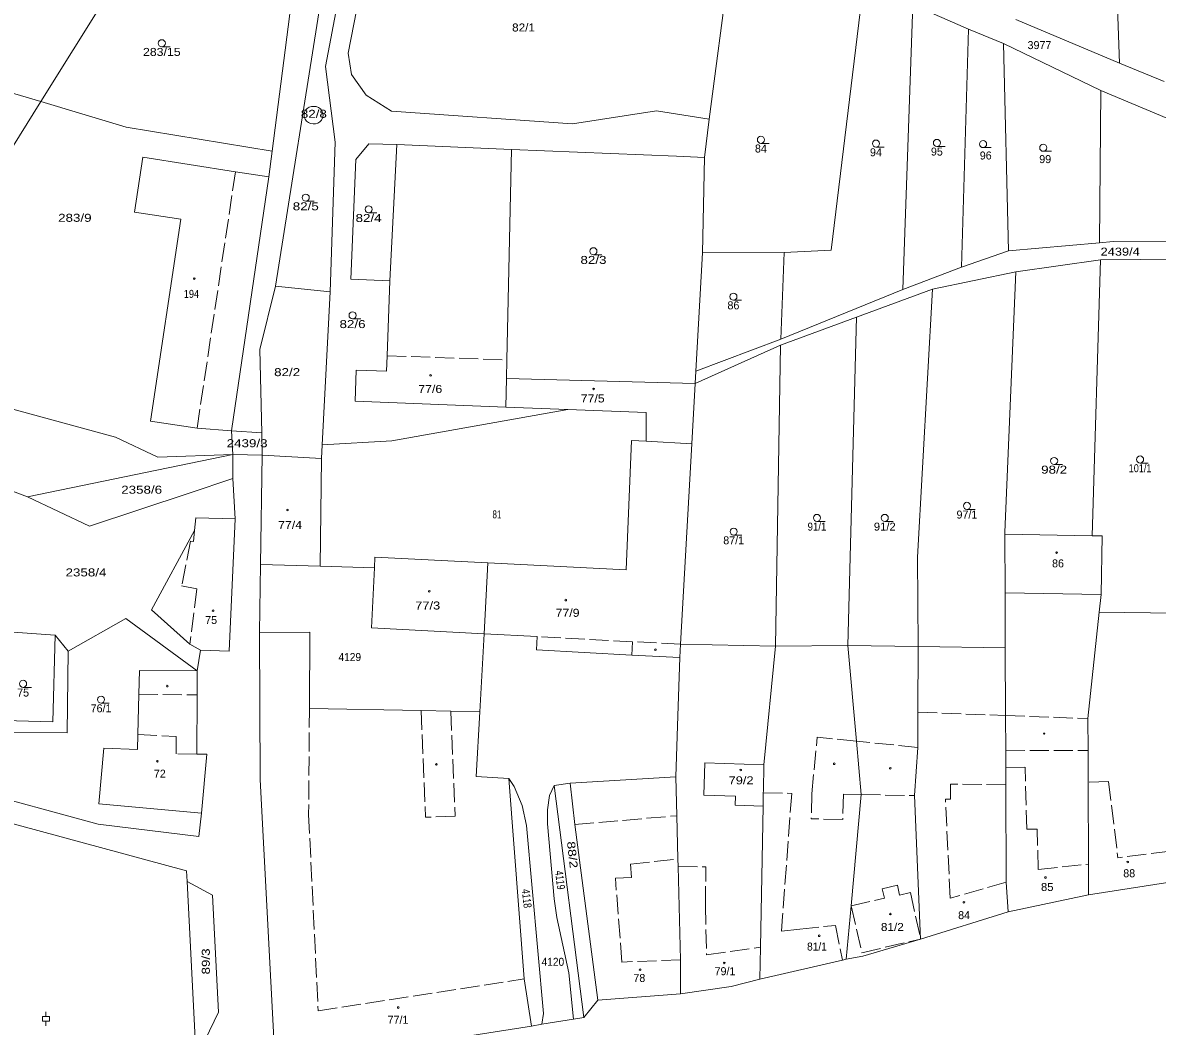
# Model space of a CAD drawing. Extents: x -590528 to -586543, y -1119609 to -1116685.
# Drawn here: x -589035.6 to -588794.5, y -1118530.4 to -1118317.2 of the extents above; entities that cross this region are included whole.
import ezdxf
from ezdxf.enums import TextEntityAlignment as Align

# ---------------------------------------------------------------- set-up
doc = ezdxf.new("R2010")
doc.units = 0
doc.header["$LTSCALE"] = 0.68
doc.linetypes.add('LONG_DASHED', pattern=[7.5, 6, -1.5])
for name, color, linetype, lineweight in [('1', 7, 'Continuous', 13), ('2', 7, 'LONG_DASHED', 13), ('3', 7, 'Continuous', 13), ('6', 7, 'Continuous', 13)]:
    doc.layers.add(name, color=color, linetype=linetype, lineweight=lineweight)

msp = doc.modelspace()

# ---------------------------------------------------------------- linework, layer by layer
at = {"layer": '1'}
for p, q in [((-588805.82, -1118234.34), (-588802.56, -1118325.8)), ((-588981.91, -1118373.18), (-588968.01, -1118285.55)), ((-588971.3, -1118326.57), (-588963.96, -1118288.22)), ((-589031.78, -1118334), (-589011.68, -1118301.83)), ((-588856.9, -1118308.63), (-588863.85, -1118365.56)), ((-588982.58, -1118344.54), (-588978.58, -1118313.12)), ((-588848.61, -1118373.89), (-588846.49, -1118313.43)), ((-588802.56, -1118325.8), (-588824.58, -1118316.52)), ((-588834.65, -1118318.61), (-588836.1, -1118369.18)), ((-588827.17, -1118321.66), (-588834.65, -1118318.61)), ((-588827.17, -1118321.66), (-588826.14, -1118365.68)), ((-588806.53, -1118331.63), (-588827.17, -1118321.66)), ((-588793.07, -1118329.73), (-588802.56, -1118325.8)), ((-588806.53, -1118331.63), (-588806.8, -1118363.98)), ((-589061.12, -1118380.96), (-589031.78, -1118334)), ((-589013.6, -1118339.4), (-588982.58, -1118344.54)), ((-588956.08, -1118343.11), (-588957.58, -1118372.06)), ((-589010.11, -1118345.81), (-589000.25, -1118347.39)), ((-588890.71, -1118345.86), (-588891.13, -1118366.13)), ((-588991.27, -1118403.96), (-588983.28, -1118349.99)), ((-589001.99, -1118358.97), (-589008.42, -1118401.89)), ((-588873.84, -1118366.08), (-588863.85, -1118365.56)), ((-588836.1, -1118369.18), (-588826.14, -1118365.68)), ((-588891.13, -1118366.13), (-588892.55, -1118391.29)), ((-588806.61, -1118367.61), (-588808.34, -1118426.23)), ((-588965.9, -1118371.75), (-588957.58, -1118372.06)), ((-588985.2, -1118386.67), (-588981.91, -1118373.18)), ((-588981.91, -1118373.18), (-588970.29, -1118374.44)), ((-588842.31, -1118373.82), (-588858.45, -1118379.78)), ((-588858.45, -1118379.78), (-588874.58, -1118385.73)), ((-588858.45, -1118379.78), (-588860.29, -1118449.57)), ((-588892.55, -1118391.29), (-588874.55, -1118384.44)), ((-589015.88, -1118405.31), (-589067.54, -1118391.23)), ((-588892.55, -1118391.29), (-588892.7, -1118393.88)), ((-588932.8, -1118392.79), (-588932.93, -1118398.9)), ((-588892.7, -1118393.88), (-588932.8, -1118392.79)), ((-588893.42, -1118406.71), (-588892.7, -1118393.88)), ((-588957.17, -1118406.04), (-588919.8, -1118399.42)), ((-588903.13, -1118400.08), (-588919.8, -1118399.42)), ((-588998.56, -1118403.37), (-589008.42, -1118401.89)), ((-588903.13, -1118400.08), (-588903.12, -1118406.15)), ((-588991.27, -1118403.96), (-588998.56, -1118403.37)), ((-588991.27, -1118403.96), (-588984.83, -1118404.33)), ((-589006.87, -1118409.52), (-589015.88, -1118405.31)), ((-588907.38, -1118433.48), (-588906.25, -1118405.97)), ((-588893.42, -1118406.71), (-588895.82, -1118449.29)), ((-589034.56, -1118417.94), (-588990.98, -1118409)), ((-588984.73, -1118409.14), (-588985.1, -1118432.32)), ((-588984.73, -1118409.14), (-588972.14, -1118409.8)), ((-588971.98, -1118406.91), (-588972.14, -1118409.8)), ((-588972.14, -1118409.8), (-588972.41, -1118432.72)), ((-588990.96, -1118414.09), (-589000.22, -1118417.16)), ((-588990.96, -1118414.09), (-588990.46, -1118422.61)), ((-589000.22, -1118417.16), (-589021.38, -1118424.19)), ((-588999.08, -1118425.14), (-589008.22, -1118441.94)), ((-588826.91, -1118425.91), (-588826.91, -1118425.44)), ((-588806.48, -1118438.73), (-588806.26, -1118426.27)), ((-588936.8, -1118431.98), (-588960.78, -1118430.76)), ((-588845.33, -1118449.79), (-588845.5, -1118430.77)), ((-588985.1, -1118432.32), (-588985.29, -1118446.76)), ((-588826.86, -1118438.38), (-588806.48, -1118438.73)), ((-589000.08, -1118449.23), (-589008.22, -1118441.94)), ((-588806.87, -1118442.44), (-588790.51, -1118442.7)), ((-589038.65, -1118446.61), (-589028.7, -1118447.34)), ((-589028.7, -1118447.34), (-589029.21, -1118465.75)), ((-589028.7, -1118447.34), (-589025.98, -1118450.74)), ((-588961.5, -1118445.79), (-588937.55, -1118447.05)), ((-588926.27, -1118447.65), (-588937.55, -1118447.05)), ((-589000.08, -1118449.23), (-588997.82, -1118450.55)), ((-588895.98, -1118452.13), (-588895.82, -1118449.29)), ((-588895.82, -1118449.29), (-588875.66, -1118449.69)), ((-588875.66, -1118449.69), (-588878.15, -1118474.93)), ((-588860.29, -1118449.57), (-588875.66, -1118449.69)), ((-588860.29, -1118449.57), (-588845.33, -1118449.79)), ((-588845.33, -1118449.79), (-588826.82, -1118450.06)), ((-588826.77, -1118464.42), (-588826.82, -1118450.06)), ((-588998.55, -1118454.9), (-588997.82, -1118450.55)), ((-588997.82, -1118450.55), (-588991.72, -1118450.74)), ((-589010.94, -1118459.87), (-589010.81, -1118454.87)), ((-588998.55, -1118454.9), (-588998.56, -1118460.06)), ((-589011.16, -1118468.47), (-589010.94, -1118459.87)), ((-588998.56, -1118460.06), (-588998.58, -1118472.6)), ((-589045.35, -1118467.89), (-589026.16, -1118468.09)), ((-589011.24, -1118471.65), (-589011.16, -1118468.47)), ((-589018.36, -1118471.33), (-589019.4, -1118483.19)), ((-589011.24, -1118471.65), (-589018.36, -1118471.33)), ((-588846.13, -1118481.43), (-588845.44, -1118471.2)), ((-589091.18, -1118472.91), (-589000.8, -1118497.42)), ((-588996.46, -1118472.6), (-588998.58, -1118472.6)), ((-588890.91, -1118481.33), (-588890.67, -1118474.48)), ((-588890.67, -1118474.48), (-588878.15, -1118474.93)), ((-588878.23, -1118480.39), (-588878.15, -1118474.93)), ((-588826.72, -1118479.17), (-588826.73, -1118475.52)), ((-588981.96, -1118538.9), (-588985.18, -1118478.05)), ((-588922.71, -1118479.27), (-588919.25, -1118478.78)), ((-588919.25, -1118478.78), (-588896.8, -1118477.46)), ((-588896.8, -1118477.46), (-588896.6, -1118485.71)), ((-588826.65, -1118499.84), (-588826.72, -1118479.17)), ((-588809.15, -1118496), (-588809.21, -1118478.56)), ((-588922.71, -1118479.27), (-588916.41, -1118528.57)), ((-588884.13, -1118481.57), (-588890.91, -1118481.33)), ((-588884.2, -1118483.49), (-588884.13, -1118481.57)), ((-588846.13, -1118481.43), (-588844.81, -1118511.93)), ((-588878.29, -1118483.7), (-588884.2, -1118483.49)), ((-588878.29, -1118483.7), (-588878.81, -1118513.66)), ((-588998.15, -1118490.12), (-588997.63, -1118485.14)), ((-589019.57, -1118487.48), (-588998.15, -1118490.12)), ((-588809.13, -1118502.53), (-588809.15, -1118496)), ((-589000.68, -1118499.71), (-589000.8, -1118497.42)), ((-588896.33, -1118496.49), (-588895.83, -1118516.34)), ((-589000.68, -1118499.71), (-588995.26, -1118502.62)), ((-588826.19, -1118506.16), (-588826.65, -1118499.84)), ((-588791.84, -1118499.82), (-588809.13, -1118502.53)), ((-588809.13, -1118502.53), (-588826.19, -1118506.16)), ((-588826.19, -1118506.16), (-588844.81, -1118511.93)), ((-588857.11, -1118515.56), (-588844.81, -1118511.93)), ((-588878.98, -1118520.45), (-588878.81, -1118513.66)), ((-588857.11, -1118515.56), (-588860.61, -1118516.19)), ((-588927.52, -1118530.39), (-588929.06, -1118520.4)), ((-588885.06, -1118521.96), (-588895.85, -1118523.57)), ((-588878.98, -1118520.45), (-588885.06, -1118521.96)), ((-588916.41, -1118528.57), (-588913.41, -1118524.9)), ((-588981.96, -1118538.9), (-588927.52, -1118530.39))]:
    msp.add_line(p, q, dxfattribs=at)
for points in [[(-588965.72, -1118328.26), (-588966.44, -1118323.73), (-588961.64, -1118299.01), (-588960.46, -1118288.38), (-588946.41, -1118290.38), (-588945.97, -1118289.05), (-588926.77, -1118295.31)], [(-588884.32, -1118298.91), (-588885.59, -1118305.94), (-588889.71, -1118337.74)], [(-588834.65, -1118318.61), (-588846.49, -1118313.43), (-588856.9, -1118308.63)], [(-588971.3, -1118326.57), (-588969.2, -1118342.6), (-588970.29, -1118374.44)], [(-589052.2, -1118327.94), (-589031.78, -1118334), (-589013.6, -1118339.4)], [(-588889.71, -1118337.74), (-588900.92, -1118335.92), (-588918.79, -1118338.71), (-588957.21, -1118336.02), (-588962.6, -1118332.65), (-588965.72, -1118328.26)], [(-588806.53, -1118331.63), (-588788.11, -1118339.36), (-588765.12, -1118349.22)], [(-588889.71, -1118337.74), (-588890.71, -1118345.86), (-588896.71, -1118345.62), (-588931.73, -1118344.18), (-588956.08, -1118343.11)], [(-588965.9, -1118371.75), (-588964.82, -1118346.26), (-588962.09, -1118342.95), (-588956.08, -1118343.11)], [(-588931.73, -1118344.18), (-588932.71, -1118388.89), (-588932.8, -1118392.79)], [(-589010.11, -1118345.81), (-589011.88, -1118357.49), (-589001.99, -1118358.97)], [(-589000.25, -1118347.39), (-588990.4, -1118348.9), (-588983.28, -1118349.99), (-588982.58, -1118344.54)], [(-588764.09, -1118369.51), (-588786.16, -1118363.82), (-588803.9, -1118363.73), (-588806.8, -1118363.98), (-588826.14, -1118365.68)], [(-588836.1, -1118369.18), (-588848.61, -1118373.89), (-588874.55, -1118384.44), (-588873.84, -1118366.08), (-588891.13, -1118366.13)], [(-588824.56, -1118370.14), (-588806.61, -1118367.61), (-588789.42, -1118367.44), (-588787.43, -1118367.9), (-588764.59, -1118372.94)], [(-588845.5, -1118430.77), (-588842.31, -1118373.82), (-588824.56, -1118370.14), (-588826.91, -1118425.44)], [(-588957.58, -1118372.06), (-588958.17, -1118388), (-588958.29, -1118391.25)], [(-588970.29, -1118374.44), (-588971.98, -1118406.91), (-588957.17, -1118406.04)], [(-588984.73, -1118409.14), (-588984.83, -1118404.33), (-588985.2, -1118386.67)], [(-588892.7, -1118393.88), (-588874.58, -1118385.73), (-588875.66, -1118449.69)], [(-588958.29, -1118391.25), (-588964.76, -1118391.04), (-588964.99, -1118397.62)], [(-588919.8, -1118399.42), (-588932.93, -1118398.9), (-588964.99, -1118397.62)], [(-589021.38, -1118424.19), (-589034.56, -1118417.94), (-589074.33, -1118402.95)], [(-588991.27, -1118403.96), (-588990.98, -1118409), (-588984.73, -1118409.14)], [(-588893.42, -1118406.71), (-588903.12, -1118406.15), (-588906.25, -1118405.97)], [(-589006.87, -1118409.52), (-588990.98, -1118409), (-588990.96, -1118414.09)], [(-588991.72, -1118450.74), (-588990.46, -1118422.61), (-588998.83, -1118422.45), (-588999.08, -1118425.14)], [(-588826.82, -1118450.06), (-588826.86, -1118438.38), (-588826.91, -1118425.91), (-588808.34, -1118426.23), (-588806.26, -1118426.27)], [(-588960.78, -1118430.76), (-588960.89, -1118433.08), (-588961.5, -1118445.79)], [(-588985.1, -1118432.32), (-588972.41, -1118432.72), (-588960.89, -1118433.08)], [(-588937.55, -1118447.05), (-588936.8, -1118431.98), (-588907.38, -1118433.48)], [(-588806.48, -1118438.73), (-588806.87, -1118442.44), (-588809.25, -1118465.08)], [(-589013.67, -1118443.8), (-589025.98, -1118450.74), (-589026.16, -1118468.09)], [(-589010.81, -1118454.87), (-588998.55, -1118454.9), (-589013.67, -1118443.8)], [(-588985.18, -1118478.05), (-588985.29, -1118446.76), (-588974.59, -1118446.72), (-588974.7, -1118462.9), (-588950.94, -1118463.37)], [(-588929.06, -1118520.4), (-588932.29, -1118477.81), (-588939.28, -1118477.41), (-588938.49, -1118463.62), (-588937.55, -1118447.05)], [(-588926.27, -1118447.65), (-588926.42, -1118450.5), (-588906.16, -1118451.58), (-588895.98, -1118452.13)], [(-588860.29, -1118449.57), (-588858.46, -1118469.87), (-588857.43, -1118481.23)], [(-588845.44, -1118471.2), (-588845.4, -1118463.73), (-588845.33, -1118449.79)], [(-588896.8, -1118477.46), (-588896.39, -1118464.47), (-588895.98, -1118452.13)], [(-588950.94, -1118463.37), (-588944.65, -1118463.5), (-588938.49, -1118463.62)], [(-588826.73, -1118475.52), (-588826.74, -1118471.81), (-588826.77, -1118464.42)], [(-589057.67, -1118465.91), (-589057.67, -1118464.97), (-589029.21, -1118465.75)], [(-588809.21, -1118478.56), (-588809.23, -1118471.88), (-588809.25, -1118465.08)], [(-589045.35, -1118467.89), (-589047.21, -1118480.01), (-589019.57, -1118487.48)], [(-589019.4, -1118483.19), (-588997.63, -1118485.14), (-588996.46, -1118472.6)], [(-588932.29, -1118477.81), (-588931.21, -1118479.48), (-588929.49, -1118483.52), (-588928.57, -1118487.77), (-588924.97, -1118527.71), (-588925.31, -1118530.03)], [(-588913.41, -1118524.9), (-588918.3, -1118487.56), (-588919.25, -1118478.78)], [(-588918.55, -1118528.92), (-588919.58, -1118519.09), (-588922.09, -1118507.35), (-588922.69, -1118503.34), (-588924.12, -1118487.46), (-588924.1, -1118484.45), (-588923.68, -1118481.4), (-588922.71, -1118479.27)], [(-588878.29, -1118483.7), (-588878.24, -1118480.86), (-588878.23, -1118480.39)], [(-588860.61, -1118516.19), (-588859.58, -1118504.86), (-588857.43, -1118481.23)], [(-588896.6, -1118485.71), (-588896.37, -1118494.89), (-588896.33, -1118496.49)], [(-588997.04, -1118571.17), (-588998.77, -1118537.29), (-589000.68, -1118499.71)], [(-588995.26, -1118502.62), (-588993.99, -1118527.48), (-588998.77, -1118537.29)], [(-588913.41, -1118524.9), (-588895.85, -1118523.57), (-588895.83, -1118516.34)], [(-588878.98, -1118520.45), (-588861.4, -1118516.37), (-588860.61, -1118516.19)], [(-588927.52, -1118530.39), (-588925.31, -1118530.03), (-588918.55, -1118528.92), (-588916.41, -1118528.57)]]:
    msp.add_lwpolyline(points, dxfattribs=at)
for centre, radius, start, end in [((-588973.9557, -1118336.8539), 1.8664, 83.36289, 271.09667), ((-588973.6538, -1118336.8685), 1.8705, 261.81777, 92.64179)]:
    msp.add_arc(centre, radius, start, end, dxfattribs=at)
at = {"layer": '2'}
for p, q in [((-588990.4, -1118348.9), (-588998.56, -1118403.37)), ((-588958.17, -1118388), (-588932.71, -1118388.89)), ((-588999.08, -1118425.14), (-588999.31, -1118427.48)), ((-588999.96, -1118427.41), (-589001.85, -1118436.87)), ((-588999.31, -1118427.48), (-588999.96, -1118427.41)), ((-588998.62, -1118437.52), (-589001.85, -1118436.87)), ((-588998.62, -1118437.52), (-589000.08, -1118449.23)), ((-588906.01, -1118448.74), (-588906.16, -1118451.58)), ((-589010.94, -1118459.87), (-588998.56, -1118460.06)), ((-588974.7, -1118462.9), (-588974.85, -1118485.42)), ((-588950.94, -1118463.37), (-588950, -1118486.05)), ((-588944.65, -1118463.5), (-588943.73, -1118485.79)), ((-588845.4, -1118463.73), (-588826.77, -1118464.42)), ((-588826.77, -1118464.42), (-588809.25, -1118465.08)), ((-588867.95, -1118481.04), (-588866.79, -1118469.02)), ((-588826.74, -1118471.81), (-588809.23, -1118471.88)), ((-588998.58, -1118472.6), (-589003.01, -1118472.59)), ((-588826.73, -1118475.52), (-588822.61, -1118475.41)), ((-588822.25, -1118488.6), (-588822.61, -1118475.41)), ((-588838.46, -1118482.2), (-588838.46, -1118479)), ((-588826.72, -1118479.17), (-588838.46, -1118479)), ((-588804.89, -1118478.42), (-588809.21, -1118478.56)), ((-588804.89, -1118478.42), (-588802.89, -1118494.63)), ((-588878.24, -1118480.86), (-588872.2, -1118480.97)), ((-588872.2, -1118480.97), (-588874.14, -1118507.02)), ((-588867.95, -1118481.04), (-588868.06, -1118486.37)), ((-588861.23, -1118481.16), (-588861.34, -1118486.51)), ((-588861.23, -1118481.16), (-588857.43, -1118481.23)), ((-588857.43, -1118481.23), (-588846.13, -1118481.43)), ((-588974.85, -1118485.42), (-588972.83, -1118527.15)), ((-588943.73, -1118485.79), (-588950, -1118486.05)), ((-588918.3, -1118487.56), (-588896.6, -1118485.71)), ((-588861.34, -1118486.51), (-588868.06, -1118486.37)), ((-588820.05, -1118488.54), (-588822.25, -1118488.6)), ((-588819.82, -1118497.12), (-588820.05, -1118488.54)), ((-588791.81, -1118493.26), (-588802.89, -1118494.63)), ((-588906.47, -1118496.03), (-588896.37, -1118494.89)), ((-588819.82, -1118497.12), (-588809.15, -1118496)), ((-588896.33, -1118496.49), (-588890.45, -1118496.56)), ((-588890.54, -1118504.76), (-588890.45, -1118496.56)), ((-588908.29, -1118516.79), (-588909.67, -1118499)), ((-588826.65, -1118499.84), (-588838.54, -1118503.23)), ((-588846.96, -1118502.05), (-588844.81, -1118511.93)), ((-588890.54, -1118504.76), (-588890.31, -1118515.25)), ((-588859.58, -1118504.86), (-588857.28, -1118514.81)), ((-588862.93, -1118509), (-588861.4, -1118516.37)), ((-588857.28, -1118514.81), (-588844.81, -1118511.93)), ((-588890.31, -1118515.25), (-588878.81, -1118513.66)), ((-588895.83, -1118516.34), (-588908.29, -1118516.79)), ((-588972.83, -1118527.15), (-588929.06, -1118520.4))]:
    msp.add_line(p, q, dxfattribs=at)
for points in [[(-588895.82, -1118449.29), (-588906.01, -1118448.74), (-588926.27, -1118447.65)], [(-589011.16, -1118468.47), (-589003, -1118468.87), (-589003.01, -1118472.59)], [(-588845.44, -1118471.2), (-588858.46, -1118469.87), (-588866.79, -1118469.02)], [(-588838.54, -1118503.23), (-588839.54, -1118482.2), (-588838.46, -1118482.2)], [(-588909.67, -1118499), (-588906.23, -1118498.84), (-588906.47, -1118496.03)], [(-588859.58, -1118504.86), (-588852.51, -1118503.26), (-588852.96, -1118501.23), (-588849.75, -1118500.5), (-588849.28, -1118502.58), (-588846.96, -1118502.05)], [(-588874.14, -1118507.02), (-588874.38, -1118510.27), (-588870.49, -1118509.84), (-588862.93, -1118509)]]:
    msp.add_lwpolyline(points, dxfattribs=at)
at = {"layer": '6'}
for p, q in [((-589006.05, -1118322.34), (-589004.3, -1118322.34)), ((-588878.75, -1118342.86), (-588877, -1118342.86)), ((-588854.31, -1118343.66), (-588852.56, -1118343.66)), ((-588841.36, -1118343.51), (-588839.61, -1118343.51)), ((-588831.54, -1118343.78), (-588829.79, -1118343.78)), ((-588818.76, -1118344.55), (-588817.01, -1118344.55)), ((-588975.46, -1118355.14), (-588973.71, -1118355.14)), ((-588962.11, -1118357.63), (-588960.36, -1118357.63)), ((-588914.33, -1118366.53), (-588912.58, -1118366.53)), ((-588884.59, -1118376.18), (-588882.84, -1118376.18)), ((-588965.52, -1118380.16), (-588963.77, -1118380.16)), ((-588816.44, -1118411.09), (-588814.69, -1118411.09)), ((-588798.18, -1118410.78), (-588796.43, -1118410.78)), ((-588834.97, -1118420.63), (-588833.22, -1118420.63)), ((-588866.84, -1118423.19), (-588865.09, -1118423.19)), ((-588852.43, -1118423.19), (-588850.68, -1118423.19)), ((-588884.54, -1118426.1), (-588882.79, -1118426.1)), ((-589035.52, -1118458.44), (-589033.77, -1118458.44)), ((-589018.96, -1118461.79), (-589017.21, -1118461.79)), ((-589030.68, -1118528.35), (-589030.68, -1118527.35)), ((-589030.68, -1118530.35), (-589030.68, -1118529.35))]:
    msp.add_line(p, q, dxfattribs=at)
msp.add_lwpolyline([(-589031.43, -1118529.35), (-589029.93, -1118529.35), (-589029.93, -1118528.35), (-589031.43, -1118528.35)], close=True, dxfattribs=at)
for centre, radius in [((-589006.05, -1118321.59), 0.75), ((-588878.75, -1118342.11), 0.75), ((-588854.31, -1118342.91), 0.75), ((-588841.36, -1118342.76), 0.75), ((-588831.54, -1118343.03), 0.75), ((-588818.76, -1118343.8), 0.75), ((-588975.46, -1118354.39), 0.75), ((-588962.11, -1118356.88), 0.75), ((-588914.33, -1118365.78), 0.75), ((-588999.1502, -1118371.6004), 0.175), ((-588884.59, -1118375.43), 0.75), ((-588965.52, -1118379.41), 0.75), ((-588948.9402, -1118392.1504), 0.175), ((-588914.2902, -1118395.0504), 0.175), ((-588816.44, -1118410.34), 0.75), ((-588798.18, -1118410.03), 0.75), ((-588979.3402, -1118420.7504), 0.175), ((-588834.97, -1118419.88), 0.75), ((-588866.84, -1118422.44), 0.75), ((-588852.43, -1118422.44), 0.75), ((-588884.54, -1118425.35), 0.75), ((-588815.9102, -1118429.8204), 0.175), ((-588949.2302, -1118438.0304), 0.175), ((-588920.2102, -1118439.9004), 0.175), ((-588995.1502, -1118442.1504), 0.175), ((-588901.1502, -1118450.4404), 0.175), ((-589035.52, -1118457.69), 0.75), ((-589004.8902, -1118458.1704), 0.175), ((-589018.96, -1118461.04), 0.75), ((-588818.5601, -1118468.2702), 0.1172), ((-589006.9902, -1118474.1504), 0.175), ((-588947.7002, -1118474.8004), 0.175), ((-588883.0202, -1118475.9904), 0.175), ((-588863.1702, -1118474.6804), 0.175), ((-588851.2702, -1118475.6304), 0.175), ((-588800.8002, -1118495.5304), 0.175), ((-588818.2902, -1118498.8404), 0.175), ((-588835.6202, -1118504.1104), 0.175), ((-588851.2402, -1118506.6004), 0.175), ((-588866.3602, -1118511.2204), 0.175), ((-588886.5302, -1118517.0004), 0.175), ((-588904.4202, -1118518.4304), 0.175), ((-588955.8102, -1118526.4604), 0.175)]:
    msp.add_circle(centre, radius, dxfattribs=at)

# ---------------------------------------------------------------- texts
at = {"layer": '3'}
for s, width, p in [('82/1', 1.1, (-588929.19, -1118319.1)), ('283/15', 1.15, (-589006.0505, -1118324.29)), ('82/8', 1.25, (-588973.7405, -1118337.44)), ('82/5', 1.25, (-588975.46, -1118357.09)), ('283/9', 1.25, (-589024.5305, -1118359.53)), ('82/4', 1.25, (-588962.11, -1118359.58)), ('2439/4', 1.2, (-588802.41, -1118366.72)), ('82/3', 1.25, (-588914.33, -1118368.48)), ('194', 0.85, (-588999.75, -1118375.69)), ('82/6', 1.25, (-588965.52, -1118382.11)), ('82/2', 1.25, (-588979.4205, -1118392.32)), ('77/6', 1.15, (-588949.011, -1118395.9)), ('77/5', 1.15, (-588914.49, -1118397.91)), ('2439/3', 1.25, (-588987.921, -1118407.42)), ('98/2', 1.25, (-588816.44, -1118413.04)), ('101/1', 0.85, (-588798.1805, -1118412.73)), ('2358/6', 1.25, (-589010.3305, -1118417.3)), ('81', 0.75, (-588934.8405, -1118422.54)), ('77/4', 1.15, (-588978.791, -1118424.79)), ('91/1', 0.9, (-588866.8405, -1118425.14)), ('91/2', 1.05, (-588852.43, -1118425.14)), ('2358/4', 1.25, (-589022.1605, -1118434.87)), ('77/3', 1.2, (-588949.5505, -1118441.9)), ('77/9', 1.15, (-588919.831, -1118443.45)), ('4129', 0.95, (-588966.11, -1118452.85)), ('79/2', 1.2, (-588882.96, -1118479.04)), ('85', 1.05, (-588817.911, -1118501.7)), ('81/2', 1.1, (-588850.82, -1118510.2)), ('81/1', 0.95, (-588866.8405, -1118514.36)), ('4120', 0.95, (-588922.9505, -1118517.6))]:
    msp.add_text(s, height=1.7, dxfattribs=dict(at, width=width)).set_placement(p, align=Align.CENTER)
for s, p in [('3977', (-588819.56, -1118322.84)), ('84', (-588878.7505, -1118344.81)), ('94', (-588854.3105, -1118345.61)), ('95', (-588841.3605, -1118345.46)), ('96', (-588830.9805, -1118346.29)), ('99', (-588818.3405, -1118347.06)), ('86', (-588884.5905, -1118378.13)), ('97/1', (-588834.9705, -1118422.58)), ('87/1', (-588884.54, -1118428.05)), ('86', (-588815.6205, -1118432.95)), ('75', (-588995.5705, -1118444.98)), ('75', (-589035.5205, -1118460.39)), ('76/1', (-589018.9605, -1118463.74)), ('72', (-589006.47, -1118477.62)), ('88', (-588800.4905, -1118498.78)), ('84', (-588835.5805, -1118507.68)), ('78', (-588904.5805, -1118521.03)), ('79/1', (-588886.3805, -1118519.59)), ('77/1', (-588955.861, -1118529.91))]:
    msp.add_text(s, height=1.7, dxfattribs=at).set_placement(p, align=Align.CENTER)
for s, rotation, width, p in [('88/2', 276.338, 1.3, (-588919.6397, -1118494.1032)), ('4119', 276.567, 0.8, (-588922.2592, -1118499.4763)), ('4118', 276.452, 0.8, (-588929.3491, -1118503.3855)), ('89/3', 90.012, 1.25, (-588995.8496, -1118516.6702))]:
    msp.add_text(s, height=1.7, rotation=rotation, dxfattribs=dict(at, width=width)).set_placement(p, align=Align.CENTER)

doc.saveas('drawing.dxf')
